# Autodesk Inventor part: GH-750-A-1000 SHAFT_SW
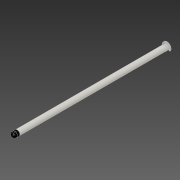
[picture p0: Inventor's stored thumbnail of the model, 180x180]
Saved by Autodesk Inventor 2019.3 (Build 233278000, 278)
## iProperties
Created: 2018-11
Part Number: GH-750-A-1000 SHAFT_SW
Material: Generic
Document SubType Name: Modeling
Designer: Justin
Density: 1 g/cm^3
Appearance: Default
Mass: 3.52583 g
Surface Area: 29.206 cm^2
Volume: 3.52583 cm^3
Author: Justin
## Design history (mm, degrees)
node "Assembly1" dims "d0" = 10
body "Solid1"
node "Part1:1" dims "d0" = 10
node "Part2:1" dims "d0" = 10
body "Solid2"
node "Part3:1" dims "d0" = 10
body "Solid3"
